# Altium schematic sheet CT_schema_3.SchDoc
size 329 x 327 mm
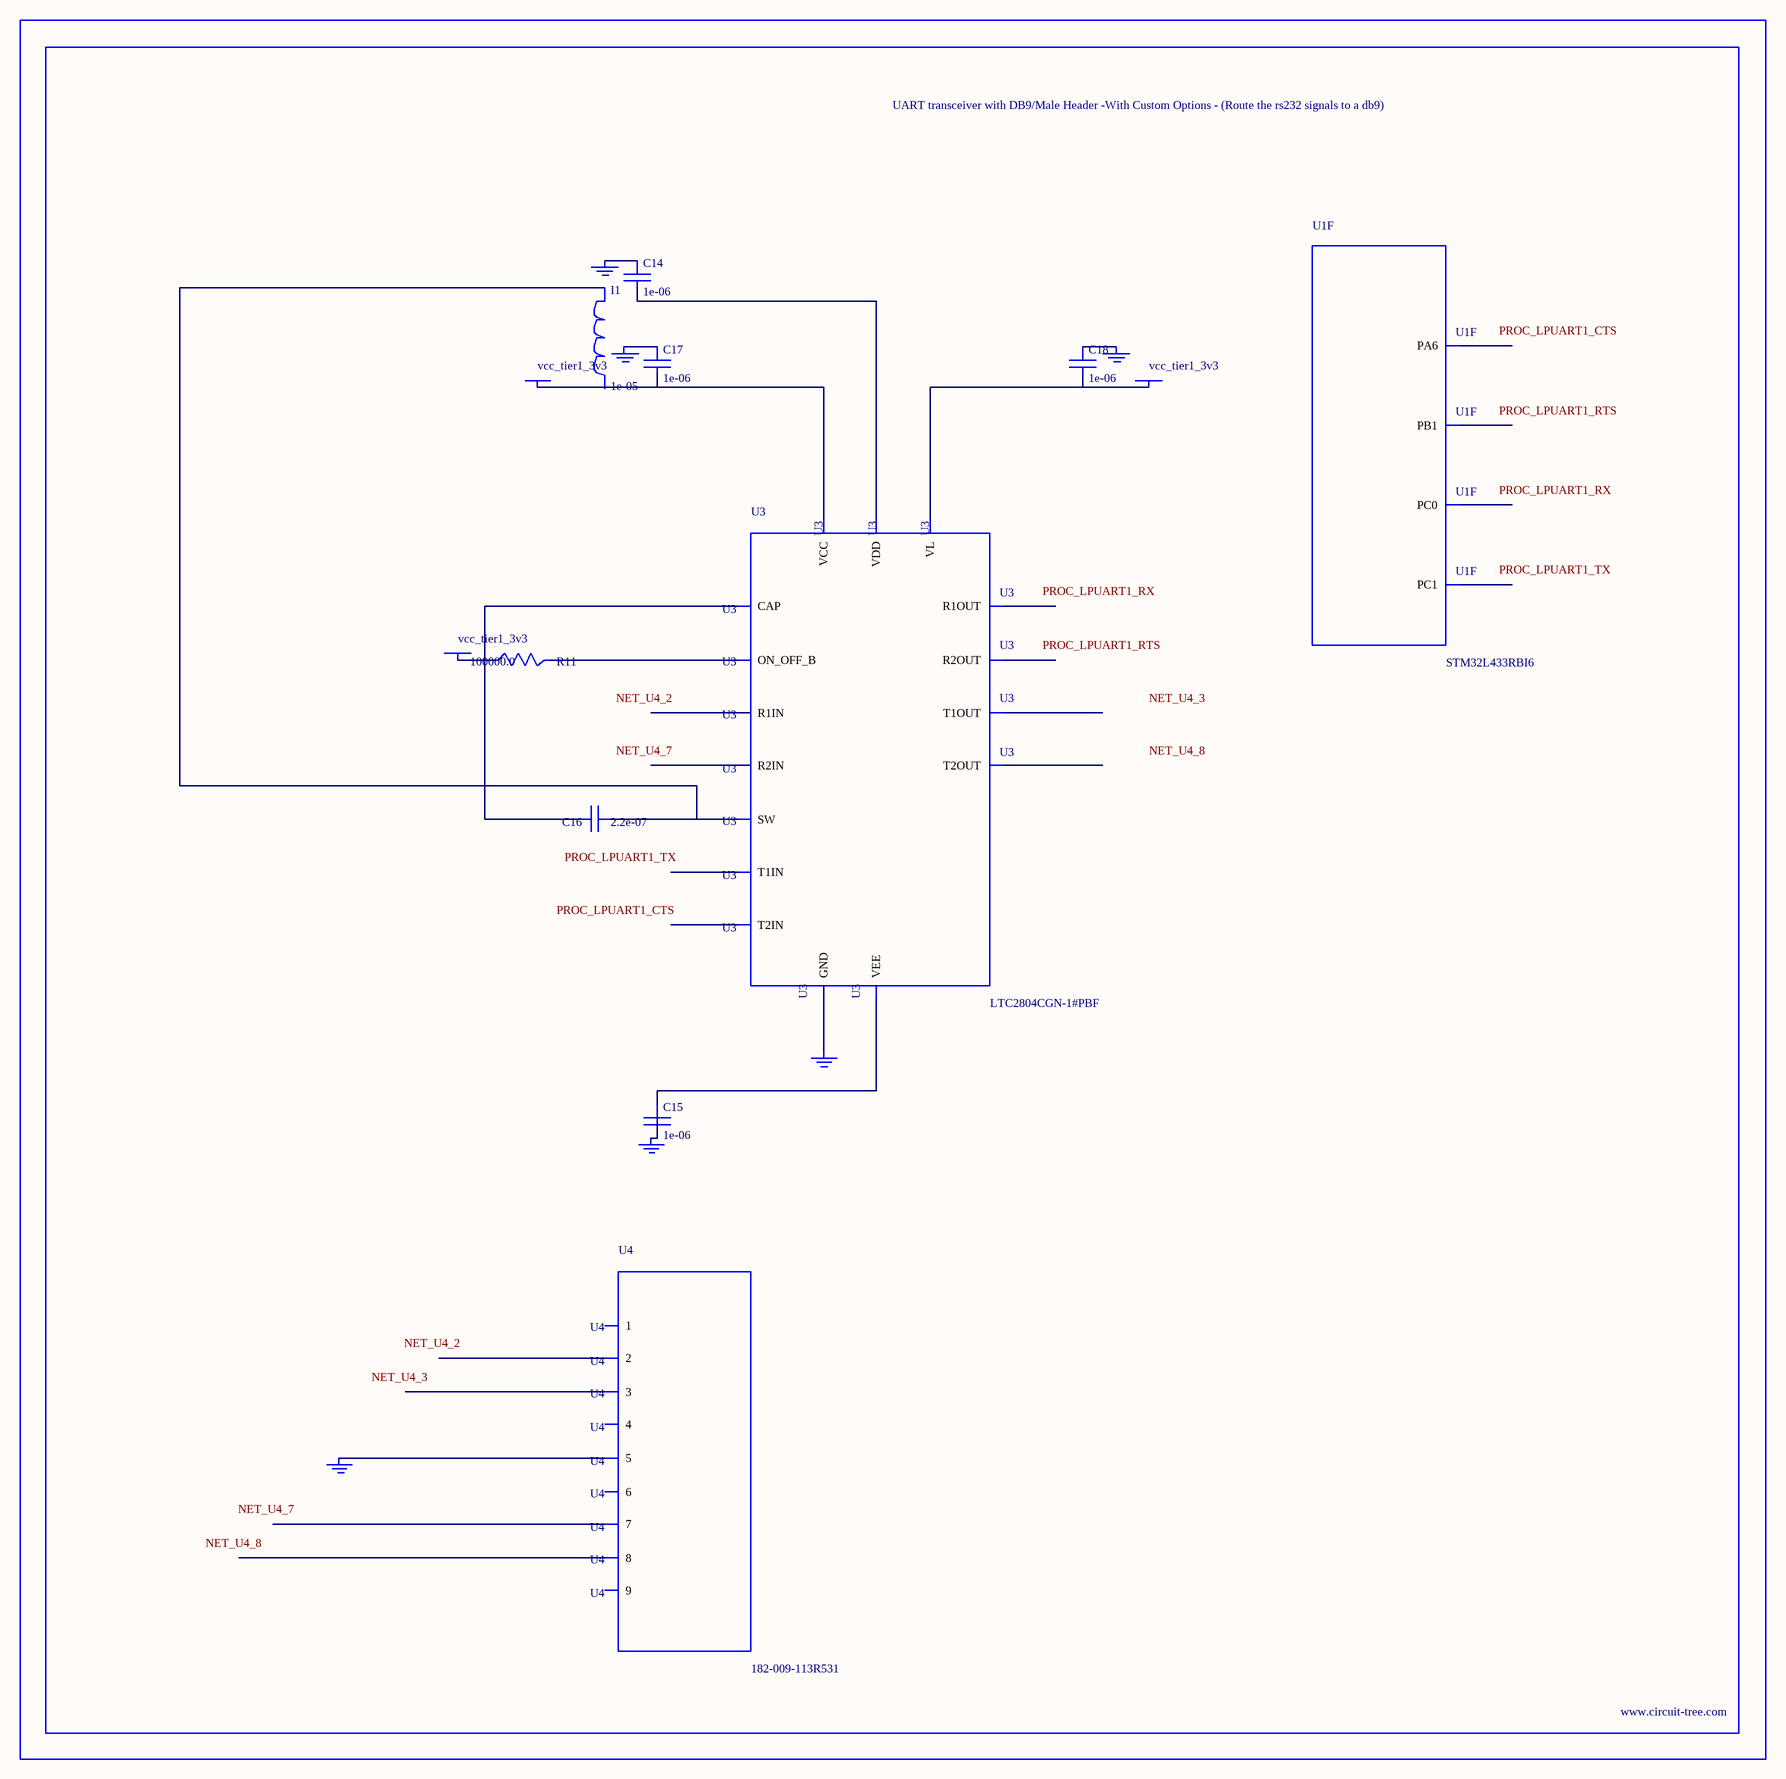
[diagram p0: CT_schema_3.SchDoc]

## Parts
BORDER2  (no value)
C14  1e-06  [C0603]
C15  1e-06  [C0603]
C16  2.2e-07  [C0603]
C17  1e-06  [C0603]
C18  1e-06  [C0603]
GND_INSTANCE_2_0  (no value)
GND_INSTANCE_2_1  (no value)
GND_INSTANCE_2_2  (no value)
GND_INSTANCE_2_3  (no value)
GND_INSTANCE_2_4  (no value)
GND_INSTANCE_2_5  (no value)
I1  1e-05  [L1210]
POWER_INSTANCE_2_0  vcc_tier1_3v3
POWER_INSTANCE_2_1  vcc_tier1_3v3
POWER_INSTANCE_2_2  vcc_tier1_3v3
R11  100000.0  [R0603]
U1  STM32L433RBI6  [UFBGA64]  (part F of 7)
U3  LTC2804CGN-1#PBF  [SSOP-16]
U4  182-009-113R531  [182-009-MALE]

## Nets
NetC14_1: C14.1 GND_INSTANCE_2_1.0(GND)
NetC14_2: C14.2 U3.6(VDD)
NetC15_1: C15.1 U3.9(VEE)
NetC15_2: C15.2 GND_INSTANCE_2_2.0(GND)
NetC16_1: C16.1 I1.1 U3.7(SW)
NetC16_2: C16.2 U3.10(CAP)
NetC17_1: C17.1 GND_INSTANCE_2_0.0(GND)
NetC17_2: C17.2 POWER_INSTANCE_2_0.0(PWR) U3.5(VCC)
NetC18_1: C18.1 GND_INSTANCE_2_3.0(GND)
NetC18_2: C18.2 POWER_INSTANCE_2_2.0(PWR) U3.12(VL)
NetGND_INSTANCE_2_4_0: GND_INSTANCE_2_4.0(GND) U3.8(GND)
NetGND_INSTANCE_2_5_0: GND_INSTANCE_2_5.0(GND) U4.5
NetPOWER_INSTANCE_2_1_0: POWER_INSTANCE_2_1.0(PWR) R11.1
NetR11_2: R11.2 U3.11(ON_OFF_B)

Not connected (* = marked no-connect by the designer): I1 2; U1 E2(PC1) E3(PC0) G4(PA6) G5(PB1); U3 1(R1IN) 2(R2IN) 3(T1OUT) 4(T2OUT) 13(T2IN) 14(T1IN) 15(R2OUT) 16(R1OUT); U4 1 2 3 4 6 7 8 9

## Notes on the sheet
- Labels drawn without touching a wire or pin: NET_U4_2, NET_U4_3, NET_U4_7, NET_U4_8, PROC_LPUART1_CTS, PROC_LPUART1_RTS, PROC_LPUART1_RX, PROC_LPUART1_TX

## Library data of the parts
BORDER2 = BORDER_PAGE2
C14 C15 C17 C18 = C0603C105K3RACTU
C16 = C0603C224K3RAC
GND_INSTANCE_2_0-GND_INSTANCE_2_5 = GND
I1 = CBC3225T100MR
POWER_INSTANCE_2_0-POWER_INSTANCE_2_2 = PWR
R11 = RC0603JR-07100KL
